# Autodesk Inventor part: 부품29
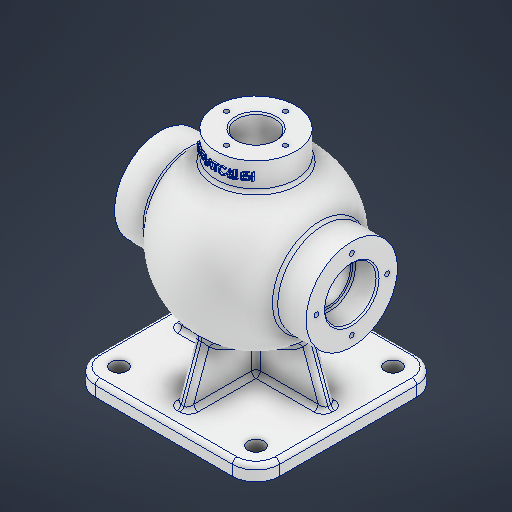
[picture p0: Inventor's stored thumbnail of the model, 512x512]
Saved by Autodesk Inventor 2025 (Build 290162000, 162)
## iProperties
Created: 2025-08
Part Number: 부품29
Material: 알루미늄 6061
Document SubType Name: Modeling
Designer: infra005
Density: 2.7 g/cm^3
Appearance: 알루미늄 - 평지
Author: infra005
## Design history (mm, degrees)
sketch "스케치1"
  geometry: L1 (46.5, 62.5)-(-46.5, 62.5); L2 (-62.5, 46.5)-(-62.5, -46.5); L3 (-46.5, -62.5)-(46.5, -62.5); L4 (62.5, -46.5)-(62.5, 46.5); L5 (62.5, 62.5)-(-62.5, -62.5); L6 (-62.5, 62.5)-(62.5, -62.5); L7 (0, -92.139)-(0, 92.139) reference; A1 r 16 centre (46.5, -46.5) between (46.5, -62.5) and (62.5, -46.5); A2 r 16 centre (-46.5, -46.5) between (-62.5, -46.5) and (-46.5, -62.5); A3 r 16 centre (-46.5, 46.5) between (-46.5, 62.5) and (-62.5, 46.5); A4 r 16 centre (46.5, 46.5) between (62.5, 46.5) and (46.5, 62.5); 1 further point
  constraints: 12 end point, 8 point on circle, 8 point on line, 8 tangent, 4 centre point, 3 equal radius, 2 midpoint, 2 parallel, 1 horizontal, 1 perpendicular
  dimensions: "d0" = 125 distance of L5.end L6.end; "d1" = 125 distance of L6.start L5.end; "d2" = 16 radius of A1
extrude "돌출1" new body sketch "스케치1" distance "d5" = 10; taper "d6" = 0 deg
sketch "스케치3"
  geometry: L1 (0, 159.709)-(0, -26.618) reference; L2 (-79.159, 85)-(102.785, 85); L3 (-115.548, 0)-(139.174, 0) reference; A1 r 54 centre (0, 85) between (0, 139) and (0, 31); 1 further point
  constraints: 4 point on line, 2 end point, 2 point on circle, 1 centre point, 1 horizontal
  dimensions: "d9" = 108 diameter of A1; "d10" = 85 distance between parallel lines of L3 L2
revolve "회전1" sketch "스케치3" stored, may be unused: angle "d11" = 90 deg
sketch "스케치4"
  geometry: L1 (-65, 116)-(0, 116); L2 (0, 116)-(0, 54); L3 (-65, 85)-(-65, 116); L4 (-153.218, 85)-(119.438, 85); L5 (-207.749, 0)-(173.969, 0) reference; L6 (0, 166.8)-(0, -27.8) reference; L7 (-65, 85)-(0, 85); 2 further points
  constraints: 10 end point, 4 point on line, 2 horizontal, 1 parallel, 1 perpendicular
  dimensions: "d13" = 85 distance between parallel lines of L5 L4; "d14" = 31 distance between parallel lines of L4 L1; "d15" = 65 distance of L1.start L1.end
revolve "회전2" sketch "스케치4" stored, may be unused: angle "d16" = 90 deg
node "작업 평면1"
sketch "스케치5"
  geometry: C1 r 27 at (0, 0); 1 further point
  constraints: 1 centre point, 1 coincident
  dimensions: "d18" = 54 diameter of C1
extrude "돌출2" join sketch "스케치5" stored distance "d19" = 10; taper "d20" = 0 deg
sketch "스케치7"
  geometry: L1 (0, 57.838)-(-33.088, 57.838); L2 (-33.088, 57.838)-(-50.5, 10); L3 (-50.5, 10)-(0, 10); L4 (0, 10)-(0, 57.838); L5 (-46.5, 10)-(-62.5, 10) reference; L6 (-62.5, 0)-(-62.5, 10) reference; 2 further points
  constraints: 8 end point, 1 horizontal, 1 midpoint, 1 parallel, 1 perpendicular, 1 point on line
  dimensions: "d24" = 20 deg angle of L4 L2; "d25" = 12 distance from line of L6 L2.end
extrude "돌출3" join sketch "스케치7" stored distance "d26" = 8; taper "d27" = 0 deg
sketch "스케치8"
  geometry: L1 (10, 4)-(10, -4) reference; L2 (10, 0)-(10, -50.5); L3 (10, -46.5)-(10, 46.5) reference; L4 (10, -50.5)-(54.069, -34.46); L5 (54.069, -34.46)-(54.069, 0); L6 (54.069, 0)-(10, 0); L7 (0, -62.5)-(10, -62.5) reference; 2 further points
  constraints: 8 end point, 1 collinear, 1 midpoint, 1 parallel, 1 perpendicular
  dimensions: "d28" = 12 distance from line of L7 L2.end; "d29" = 20 deg angle of L7 L4
extrude "돌출4" join sketch "스케치8" stored distance "d30" = 8; taper "d31" = 0 deg
sketch "스케치9"
  geometry: L1 (-65, 54)-(-65, 116) reference; L2 (-65, 102.5)-(-49, 102.5); L3 (-49, 102.5)-(-49, 100); L4 (-49, 100)-(0, 100); L5 (-88.477, 85)-(100.893, 85); L6 (-126.351, 0)-(138.767, 0) reference; L7 (-65, 102.5)-(-65, 85); L8 (0, 85)-(0, 100); L9 (-65, 85)-(0, 85); 1 further point
  constraints: 14 end point, 3 point on line, 2 horizontal, 2 perpendicular, 1 collinear, 1 midpoint, 1 parallel
  dimensions: "d32" = 85 distance between parallel lines of L6 L5; "d33" = 17.5 distance between parallel lines of L5 L2; "d34" = 15 distance between parallel lines of L5 L4; "d35" = 16 distance between parallel lines of L1 L3
revolve "회전3" sketch "스케치9" stored, may be unused: angle "d36" = 90 deg
sketch "스케치10"
  geometry: L1 (0, 100)-(0, 70) reference; L2 (0, 155.587)-(0, 20.929); L3 (0, 129)-(0, 40.639); A1 r 44 centre (0, 85) between (0, 129) and (0, 41); 4 further points
  constraints: 4 end point, 3 point on line, 2 point on circle, 1 centre point, 1 midpoint, 1 vertical
  dimensions: "d37" = 44 radius of A1
revolve "회전4" sketch "스케치10" stored, may be unused: angle "d38" = 90 deg
sketch "스케치11" dims "d39" = 48
  geometry: L1 (0, 0)-(0, 24); C1 r 31 at (0, 0) reference; 3 further points
  constraints: 2 end point, 1 coincident, 1 vertical, 1 vertical alignment, 3 other
hole "구멍1" sketch "스케치11" at (0, 24) diameter "d40" = 3.242; stored, may be unused: countersink angle "d44" = 90 deg, drill point angle "d46" = 118 deg; dims "d41" = 12, "d42" = 4, "d43" = 2, "d45" = 15
sketch "스케치12"
  geometry: C1 r 13 at (0, 0); 1 further point
  constraints: 1 centre point, 1 coincident
  dimensions: "d50" = 26 diameter of C1
extrude "돌출5" cut sketch "스케치12" stored distance "d51" = 8; taper "d52" = 0 deg
sketch "스케치13"
  geometry: L1 (0, 0)-(0, 20); L2 (0, 87.5)-(0, -87.5) reference; A1 r 20 centre (0, 0) between (0, 20) and (0, 20); 1 further point
  constraints: 2 coincident, 2 end point, 2 point on circle, 1 centre point, 1 point on line
  dimensions: "d53" = 40 diameter of A1
hole "구멍2" sketch "스케치13" at (0, 20) diameter "d54" = 3.242; stored, may be unused: countersink angle "d58" = 90 deg, drill point angle "d60" = 118 deg; dims "d55" = 9, "d56" = 4, "d57" = 2, "d59" = 11
sketch "스케치14"
  geometry: C1 r 5.5 at (-46.5, 46.5); A1 r 16 centre (-46.5, 46.5) between (-46.5, 62.5) and (-62.5, 46.5) reference; 1 further point
  constraints: 1 centre point, 1 concentric
  dimensions: "d64" = 11 diameter of C1
extrude "돌출6" cut sketch "스케치14" distance "d65" = 10; taper "d66" = 0 deg
chamfer "모따기1" distance "d73" = 1; stored, may be unused: second distance "d74" = 2, angle "d75" = 45 deg
node "작업 평면2"
sketch "스케치15" dims "d0" = 125, "d1" = 125, "d2" = 16
  geometry: L1 (27, 150)-(-27, 150) reference; L2 (0, 180)-(0, -30) reference; 2 further points
  constraints: 1 point on line, 1 other
  dimensions: "d77" = 9 distance from line of L1 point (0, 141)
feature "엠보싱1" sketch "스케치15" dims "d0" = 125, "d1" = 125, "d2" = 16, "d9" = 108, "d10" = 85, "d78" = 1, "d79" = 0
fillet "모깎기1" dims "d80" = 3
fillet "모깎기2" dims "d81" = 3
node "솔리드1"
mirror "미러1"
mirror "미러2"
pattern_circular "원형 패턴1" dims angle "d48" = 360 deg
mirror "미러3"
mirror "미러4"
pattern_circular "원형 패턴2" dims angle "d62" = 360 deg
pattern_linear "직사각형 패턴1" dims "d69" = -93, "d72" = 93
feature "A9D066F2-1C7D-4E18-AEED-F7BC21143FA4" dims "d40" = 3.242, "d41" = 12, "d42" = 4, "d43" = 2, "d44" = 90 deg, "d45" = 15, "d46" = 118 deg
other parameters: "d76" = 27.5
